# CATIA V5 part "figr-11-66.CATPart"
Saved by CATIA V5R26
Part number: Part2
Bounding box of the stored display mesh (mm): x -101 to 134, y -101.296 to 100.099, z -60.219 to 83.072
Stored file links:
  D:\_Deepak\CATIA\CATIA V5-6R2016_Deepak\Resources\Part files\Partfiles\c11_catia_v5_6r2016_prt\figr-11-66.CATPart
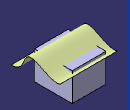
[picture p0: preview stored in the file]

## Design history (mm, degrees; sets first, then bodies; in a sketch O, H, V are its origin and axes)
Set1
  Extrude1: Element1 Sketch2, Lim1 134, Lim2 101, Direction yz-plane
Body1 (main body)
  Sketch1 on yz-plane, origin (0, 0, 0), H (0, 1, 0), V (0, 0, 1)
    line L1 (-70.5879, 56.2311) -> (84.546, 56.2311)
    line L2 (84.546, 56.2311) -> (84.546, -60.2191)
    line L3 (84.546, -60.2191) -> (-70.5879, -60.2191)
    line L4 (-70.5879, -60.2191) -> (-70.5879, 56.2311)
    horizontal: L1 H, L3 H
    vertical: L2 V, L4 V
  Pad1: profile Sketch1, direction (1, 0, 0), length 69, mirrored extent
  Sketch2 on yz-plane, origin (0, 0, 0), H (0, 1, 0), V (0, 0, 1)
    spline S1 through (-101.2957, 16.3509) (-51.8443, 49.0526) (-38.418, 74.5863) (34.1283, 62.9515) (100.0993, 49.0526)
